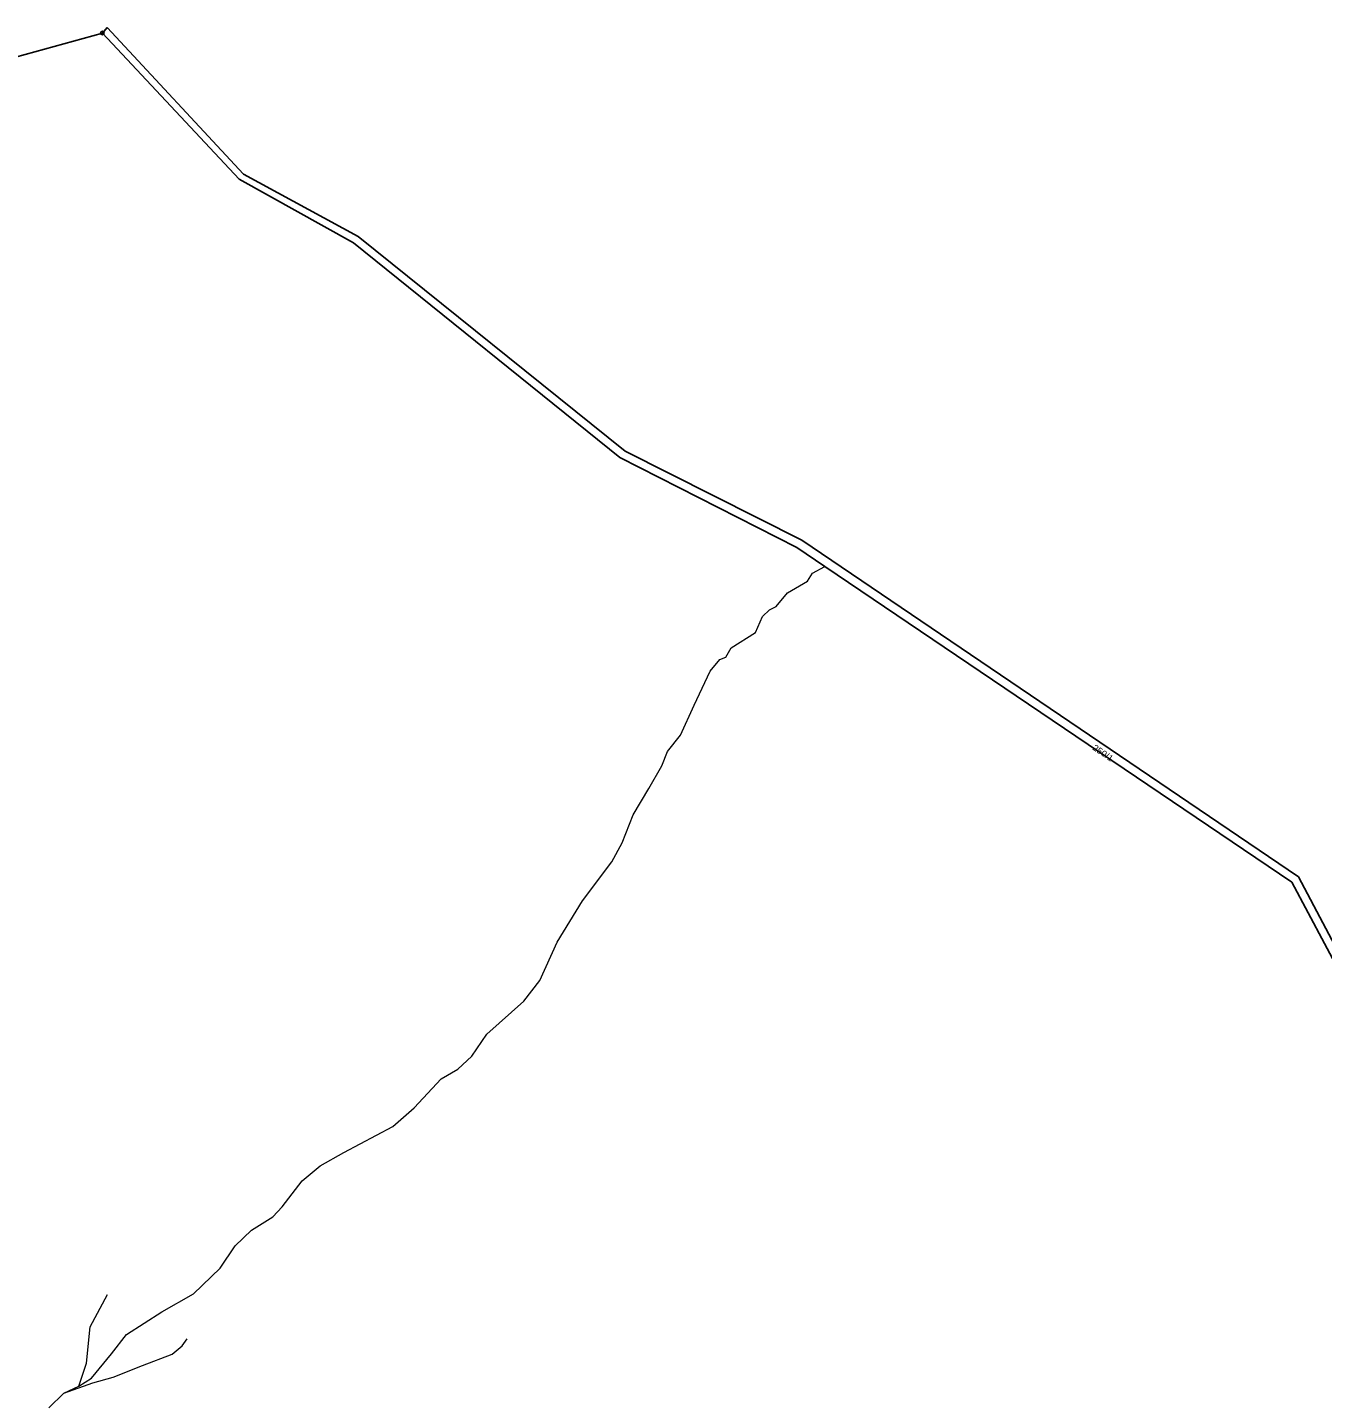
# Model space of a CAD drawing. Extents: x -632162 to -629607, y -1101195 to -1098670.
# Drawn here: x -630521.9 to -630162.6, y -1099506.1 to -1099125.1 of the extents above; entities that cross this region are included whole.
import ezdxf
from ezdxf.enums import TextEntityAlignment as Align

# ---------------------------------------------------------------- set-up
doc = ezdxf.new("R2010")
doc.units = 0
doc.header["$LTSCALE"] = 0.68
for name, color, linetype, lineweight in [('1', 7, 'Continuous', 25), ('4', 7, 'Continuous', 13), ('8', 7, 'Continuous', 25)]:
    doc.layers.add(name, color=color, linetype=linetype, lineweight=lineweight)
doc.layers.add('2', color=7, linetype='Continuous')

msp = doc.modelspace()

# ---------------------------------------------------------------- linework, layer by layer
at = {"layer": '1'}
msp.add_line((-630499.78, -1099125.05), (-630501.14, -1099126.59), dxfattribs=at)
for points in [[(-630551.15, -1099178.98), (-630541.43, -1099155.27), (-630527.89, -1099134.01), (-630501.14, -1099126.59)], [(-630501.14, -1099126.59), (-630463.21, -1099167.13), (-630431.46, -1099184.83), (-630357.58, -1099244.39), (-630308.45, -1099269.35), (-630300.72, -1099274.58), (-630171.15, -1099362.18), (-630112.25, -1099472.84), (-630065.39, -1099467.25), (-630044.03, -1099476.42), (-630041.38, -1099478.83), (-630035.86, -1099480.82)], [(-630065.49, -1099464.72), (-630111.13, -1099470.75), (-630169.31, -1099360.73), (-630307.12, -1099267.3), (-630356.12, -1099242.6), (-630430.2, -1099183.06), (-630461.99, -1099165.8), (-630499.78, -1099125.05)]]:
    msp.add_lwpolyline(points, dxfattribs=at)
at = {"layer": '4'}
for p, q in [((-630304.15, -1099276.47), (-630300.72, -1099274.58)), ((-630311.05, -1099281.9), (-630305.55, -1099278.68)), ((-630305.55, -1099278.68), (-630304.15, -1099276.47)), ((-630314.24, -1099285.68), (-630311.05, -1099281.9)), ((-630318.02, -1099288.53), (-630316.04, -1099286.67)), ((-630316.04, -1099286.67), (-630314.24, -1099285.68)), ((-630319.93, -1099292.94), (-630318.02, -1099288.53)), ((-630326.67, -1099297.18), (-630319.93, -1099292.94)), ((-630328.12, -1099299.8), (-630326.67, -1099297.18)), ((-630332.52, -1099303.67), (-630329.81, -1099300.44)), ((-630329.81, -1099300.44), (-630328.12, -1099299.8)), ((-630336.99, -1099313.14), (-630332.52, -1099303.67)), ((-630340.76, -1099321.44), (-630336.99, -1099313.14)), ((-630344.37, -1099325.98), (-630340.76, -1099321.44)), ((-630345.93, -1099329.93), (-630344.37, -1099325.98)), ((-630349.5, -1099336.23), (-630345.93, -1099329.93)), ((-630353.86, -1099343.55), (-630349.5, -1099336.23)), ((-630356.88, -1099351.28), (-630353.86, -1099343.55)), ((-630359.78, -1099356.57), (-630356.88, -1099351.28)), ((-630367.96, -1099367.39), (-630359.78, -1099356.57)), ((-630374.93, -1099378.89), (-630367.96, -1099367.39)), ((-630379.81, -1099389.47), (-630374.93, -1099378.89)), ((-630384.22, -1099395.26), (-630379.81, -1099389.47)), ((-630394.44, -1099404.38), (-630384.22, -1099395.26)), ((-630398.62, -1099410.54), (-630394.44, -1099404.38)), ((-630402.48, -1099414.07), (-630398.62, -1099410.54)), ((-630407.13, -1099416.8), (-630402.48, -1099414.07)), ((-630414.62, -1099424.81), (-630407.13, -1099416.8)), ((-630420.53, -1099430.01), (-630414.62, -1099424.81)), ((-630434.18, -1099437.27), (-630420.53, -1099430.01)), ((-630440.74, -1099440.93), (-630434.18, -1099437.27)), ((-630445.72, -1099445.09), (-630440.74, -1099440.93)), ((-630451.24, -1099452.35), (-630445.72, -1099445.09)), ((-630453.85, -1099455.08), (-630451.24, -1099452.35)), ((-630459.72, -1099458.8), (-630453.85, -1099455.08)), ((-630475.82, -1099476.48), (-630468.43, -1099469.37)), ((-630504.51, -1099485.6), (-630499.69, -1099476.65)), ((-630484.65, -1099481.42), (-630475.82, -1099476.48)), ((-630494.47, -1099487.75), (-630484.65, -1099481.42)), ((-630505.56, -1099495.65), (-630504.51, -1099485.6)), ((-630498.59, -1099493.09), (-630494.47, -1099487.75)), ((-630478.96, -1099490.89), (-630477.62, -1099488.91)), ((-630481.75, -1099493.21), (-630478.96, -1099490.89)), ((-630507.69, -1099502.07), (-630505.56, -1099495.65)), ((-630504.17, -1099499.83), (-630498.59, -1099493.09)), ((-630498.18, -1099499.54), (-630489.99, -1099496.35)), ((-630489.99, -1099496.35), (-630481.75, -1099493.21)), ((-630507.69, -1099502.07), (-630504.17, -1099499.83)), ((-630503.82, -1099501.11), (-630498.18, -1099499.54)), ((-630515.99, -1099508.06), (-630511.87, -1099504.05)), ((-630511.87, -1099504.05), (-630503.82, -1099501.11)), ((-630511.87, -1099504.05), (-630507.69, -1099502.07))]:
    msp.add_line(p, q, dxfattribs=at)
msp.add_lwpolyline([(-630468.43, -1099469.37), (-630464.25, -1099463.1), (-630459.72, -1099458.8)], dxfattribs=at)
at = {"layer": '8'}
for radius in [0.5, 0.0303]:
    msp.add_circle((-630501.14, -1099126.5899), radius, dxfattribs=at)

# ---------------------------------------------------------------- texts
at = {"layer": '2', "width": 1.1}
msp.add_text('250/1', height=1.7, rotation=326, dxfattribs=at).set_placement((-630223.9978, -1099327.0576), align=Align.CENTER)

doc.saveas('drawing.dxf')
